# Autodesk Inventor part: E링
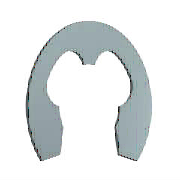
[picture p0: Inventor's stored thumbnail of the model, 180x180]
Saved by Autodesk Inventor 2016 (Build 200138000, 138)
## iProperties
Created: 2012-02
Part Number: E링
Material: 강철, 연강
Description: 스프링 리테이닝 링
Document SubType Name: Modeling
Standard: JIS B 2805
Designer: mduedu
Standards Organization: JIS
Language: ko-KR
Size Designation: 4
Categories: <MemberInstance><Categories><Category DisplayName="샤프트 부품" InternalName="7f7aeb1f-a693-4053-b835-cee3144e0d98" Mnemonic="SHFT"><Category DisplayName="써클립" Inter
Density: 1 g/cm^3
Appearance: 노란색
IsCustomPart: 1
Author: mduedu
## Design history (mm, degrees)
sketch "스케치1"
  geometry: L1 (-0.4, 0.024)-(0, 0.024) reference; L2 (-3.206, 0)-(3.486, 0) reference; L3 (-1.833, -3.276)-(1.833, -3.276); L4 (0, 1.949)-(0, -3.479) reference; L5 (-2.4, -1.676)-(-2.008, -1.676); L6 (-0.4, -0.076)-(-0.4, 0.312); L7 (0, 2.024)-(2.53, 2.024); L8 (-1.833, -3.276)-(-2.47, -5.119); L9 (0, -0.476)-(-1.278, -0.476); L10 (1.833, -3.276)-(2.47, -5.119); L11 (2.4, -1.676)-(2.008, -1.676); L12 (0.4, -0.076)-(0.4, 0.312); C1 r 2.5 at (0, -2.476); A1 r 2 centre (0, -2.476) between (-1.894, -1.835) and (-1.833, -3.276); A2 r 0.4 centre (0, -0.076) between (-0.4, -0.076) and (0.4, -0.076); A3 r 4.5 centre (0, -2.476) between (3.505, -5.299) and (-3.505, -5.299); A4 r 3.2 centre (0, -2.476) between (-0.8, 0.622) and (-2.824, -0.97); A5 r 0.32 centre (-0.72, 0.312) between (-0.4, 0.312) and (-0.8, 0.622); A6 r 0.48 centre (-2.4, -1.196) between (-2.824, -0.97) and (-2.4, -1.676); A7 r 0.12 centre (-2.008, -1.796) between (-1.894, -1.835) and (-2.008, -1.676); A8 r 0.6 centre (-3.037, -4.923) between (-3.505, -5.299) and (-2.47, -5.119); A9 r 0.6 centre (3.037, -4.923) between (2.47, -5.119) and (3.505, -5.299); A10 r 2 centre (0, -2.476) between (1.833, -3.276) and (1.894, -1.835); A11 r 0.12 centre (2.008, -1.796) between (2.008, -1.676) and (1.894, -1.835); A12 r 0.48 centre (2.4, -1.196) between (2.4, -1.676) and (2.824, -0.97); A13 r 3.2 centre (0, -2.476) between (2.824, -0.97) and (0.8, 0.622); A14 r 0.32 centre (0.72, 0.312) between (0.8, 0.622) and (0.4, 0.312); 1 further point
  constraints: 30 point on circle, 20 end point, 15 centre point, 13 symmetric about line, 12 tangent, 8 point on line, 4 parallel, 2 coincident, 2 horizontal, 1 concentric, 1 perpendicular, 1 vertical alignment, 9 other
  dimensions: "d0" = 5 diameter of C1 (= WD); "d3" = 0.8 distance from line of A1.centre L3 (= 0.2 x ND); "d4" = 0.4 radius of A2 (= 0.1 x ND); "d5" = 9 diameter of A3 (= SD2); "d8" = 3.2 radius of A4 (= 0.8 x ND); "d9" = 0.8 distance from line of A1.centre L5 (= 0.2 x ND); "d10" = 0.32 radius of A5 (= 0.08 x ND); "d11" = 0.48 radius of A6 (= 0.12 x ND); "d12" = 0.12 radius of A7 (= 0.03 x ND); "d13" = 0.6 radius of A8 (= 0.15 x ND); "d14" = 2 distance from line of A1.centre L9 (= 0.5 x ND); "d15" = 2 radius of A1 (= 0.5 x ND)
extrude "본체" new body sketch "스케치1" distance "d16" = 0.6 (= SD); taper "d17" = 0 deg
workaxis "Work Axis1"
workaxis "Work Axis2"
workplane "Work Plane1"
body "Solid1"
other parameters: "ND" = 4 [user parameter; used in 14 equation terms], "SD" = 0.6 [user parameter; used in 1 equation term], "WD" = 5 (= WDMIN) [user parameter; used in 1 equation term], "d1" = 6.4 (= 1.6 x ND), "d2" = 4 (= ND), "SD2" = 9 [user parameter; used in 1 equation term], "d6" = 4 (= ND), "d7" = 0.6 (= 0.15 x ND), "d18" = 0, "d19" = 0, "d27" = 0, "d28" = 0, "WDMIN" = 5 [user parameter; used in 1 equation term], "SNB" = 0.7 [user parameter], "WDMAX" = 7 [user parameter], "BUBRMI" = 1.2 [user parameter]
